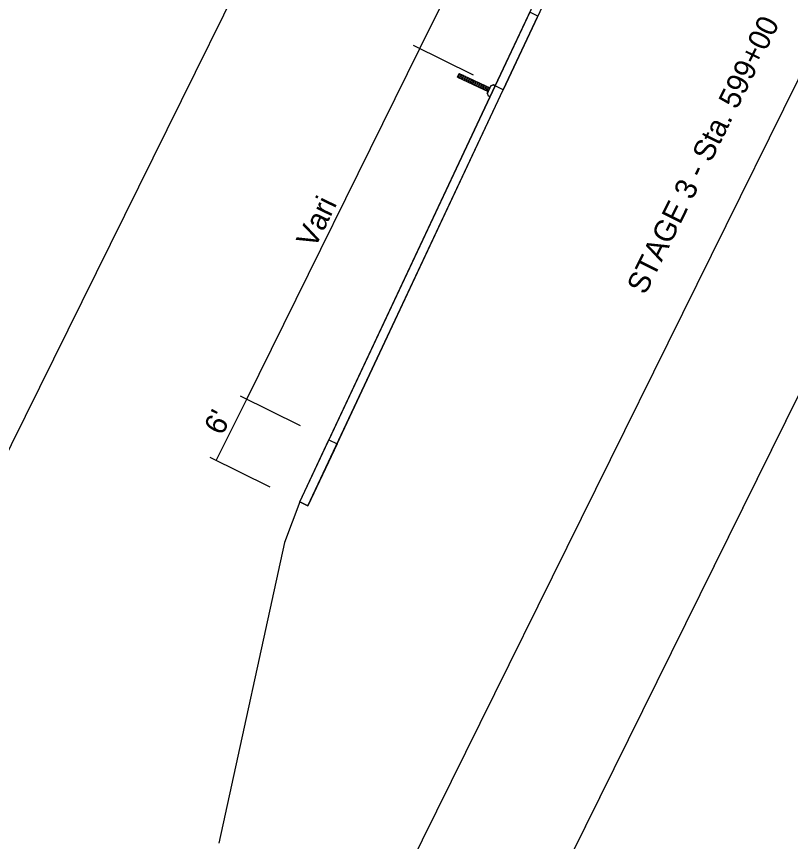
# Model space of a CAD drawing. Extents: x 14104283 to 14121738, y 8635219 to 8671666.
# Drawn here: x 14118056.1 to 14118343, y 8668202 to 8668507.7 of the extents above; entities that cross this region are included whole.
import ezdxf

# ---------------------------------------------------------------- set-up
doc = ezdxf.new("R2010")
doc.units = 0
for name, color, linetype in [('Cell', 7, 'Continuous'), ('Default', 7, 'Continuous'), ('dsnNonPlotable', 7, 'Continuous'), ('dsnStgShadingPrevPav', 7, 'Continuous'), ('dsnTextFinalPlan', 7, 'Continuous'), ('dsnTextOverlapEven', 7, 'Continuous'), ('TC_SubstrataExistingPavement', 7, 'Continuous'), ('Terrain', 7, 'Continuous')]:
    doc.layers.add(name, color=color, linetype=linetype)

msp = doc.modelspace()

# ---------------------------------------------------------------- linework, layer by layer
at = {"layer": 'Cell'}
for p, q in [((14118219.58, 8668485.3), (14118220.21, 8668486.64)), ((14118219.58, 8668485.3), (14118230.92, 8668480.01)), ((14118220.26, 8668484.99), (14118219.9, 8668485.98)), ((14118220.21, 8668486.64), (14118231.55, 8668481.35)), ((14118220.98, 8668484.65), (14118220.26, 8668486.62)), ((14118221.7, 8668484.31), (14118220.98, 8668486.29)), ((14118222.42, 8668483.98), (14118221.7, 8668485.95)), ((14118223.13, 8668483.64), (14118222.42, 8668485.61)), ((14118223.85, 8668483.31), (14118223.14, 8668485.28)), ((14118224.57, 8668482.97), (14118223.86, 8668484.94)), ((14118225.29, 8668482.64), (14118224.57, 8668484.61)), ((14118226.01, 8668482.3), (14118225.29, 8668484.27)), ((14118226.73, 8668481.97), (14118226.01, 8668483.94)), ((14118227.45, 8668481.63), (14118226.73, 8668483.6)), ((14118228.17, 8668481.29), (14118227.45, 8668483.27)), ((14118228.89, 8668480.96), (14118228.17, 8668482.93)), ((14118229.6, 8668480.62), (14118228.89, 8668482.59)), ((14118230.32, 8668480.29), (14118229.61, 8668482.26)), ((14118230.98, 8668480.13), (14118230.33, 8668481.92)), ((14118230.61, 8668479.34), (14118231.87, 8668482.02)), ((14118231.55, 8668481.35), (14118230.92, 8668480.01)), ((14118231.31, 8668480.84), (14118231.04, 8668481.59)), ((14118231.87, 8668482.02), (14118231.55, 8668481.35)), ((14118231.63, 8668478.04), (14118233.51, 8668482.07)), ((14118231.63, 8668478.04), (14118233.51, 8668482.07)), ((14118232.85, 8668482.38), (14118231.87, 8668482.02)), ((14118231.87, 8668482.02), (14118232.85, 8668482.38)), ((14118233.51, 8668482.07), (14118232.85, 8668482.38)), ((14118232.85, 8668482.38), (14118233.51, 8668482.07)), ((14118230.92, 8668480.01), (14118230.61, 8668479.34)), ((14118230.61, 8668479.34), (14118230.96, 8668478.35)), ((14118230.61, 8668479.34), (14118230.96, 8668478.35)), ((14118230.96, 8668478.35), (14118231.63, 8668478.04)), ((14118230.96, 8668478.35), (14118231.63, 8668478.04))]:
    msp.add_line(p, q, dxfattribs=at)
at = {"layer": 'Default'}
msp.add_lwpolyline([(14118174.89, 8668349.44), (14118236.5, 8668480.6), (14118249.33, 8668507.9), (14118246.34, 8668509.38), (14118233.51, 8668482.07), (14118171.9, 8668350.92)], close=True, dxfattribs=at)
at = {"layer": 'dsnNonPlotable'}
msp.add_lwpolyline([(14118092.03, 8667853.71), (14118786.76, 8669258.84), (14119692.14, 8668811.2), (14118997.41, 8667406.07)], close=True, dxfattribs=at)
at = {"layer": 'dsnStgShadingPrevPav'}
msp.add_lwpolyline([(14118161.08, 8668327.89), (14118171.9, 8668350.92), (14118174.89, 8668349.44), (14118164.07, 8668326.41)], close=True, dxfattribs=at)
at = {"layer": 'dsnTextFinalPlan'}
for p, q in [((14118205.63, 8668495.86), (14118226.9, 8668538.89)), ((14118203.17, 8668497.07), (14118225.4, 8668486.08)), ((14118141.41, 8668365.99), (14118205.63, 8668495.86)), ((14118130.14, 8668343.18), (14118141.41, 8668365.99)), ((14118138.96, 8668367.2), (14118161.19, 8668356.21)), ((14118127.69, 8668344.4), (14118149.92, 8668333.4))]:
    msp.add_line(p, q, dxfattribs=at)
for points in [[(14117870.36, 8667977.42), (14118384.92, 8669018.16), (14118565.56, 8668928.85), (14118050.99, 8667888.12)], [(14118092.03, 8667853.71), (14118606.59, 8668894.44), (14118787.23, 8668805.14), (14118272.66, 8667764.4)]]:
    msp.add_lwpolyline(points, close=True, dxfattribs=at)
at = {"layer": 'dsnTextOverlapEven'}
msp.add_lwpolyline([(14117870.36, 8667977.42), (14118384.92, 8669018.16), (14118565.56, 8668928.85), (14118050.99, 8667888.12)], close=True, dxfattribs=at)
at = {"layer": 'TC_SubstrataExistingPavement'}
for p, q in [((14118164.07, 8668326.41), (14118236.5, 8668480.6)), ((14118171.9, 8668350.92), (14118174.89, 8668349.44)), ((14118161.08, 8668327.89), (14118164.07, 8668326.41))]:
    msp.add_line(p, q, dxfattribs=at)
msp.add_lwpolyline([(14118289.97, 8668602.25), (14118292.96, 8668600.77), (14118236.5, 8668480.6), (14118233.51, 8668482.07)], dxfattribs=at)
at = {"layer": 'Terrain'}
for p, q in [((14118233.51, 8668482.07), (14118289.97, 8668602.25)), ((14118161.08, 8668327.89), (14118233.51, 8668482.07)), ((14118161.08, 8668327.89), (14118155.41, 8668312.82)), ((14118155.41, 8668312.82), (14118131.11, 8668201.36))]:
    msp.add_line(p, q, dxfattribs=at)

# ---------------------------------------------------------------- texts
at = {"layer": 'dsnTextFinalPlan'}
for s, p in [('STAGE 3 - Sta. 599+00', (14118289.14, 8668404.27)), ('Vari', (14118166.61, 8668421.42)), ("6'", (14118132.36, 8668352.15))]:
    msp.add_text(s, height=8, rotation=63.6911, dxfattribs=at).set_placement(p)

doc.saveas('drawing.dxf')
